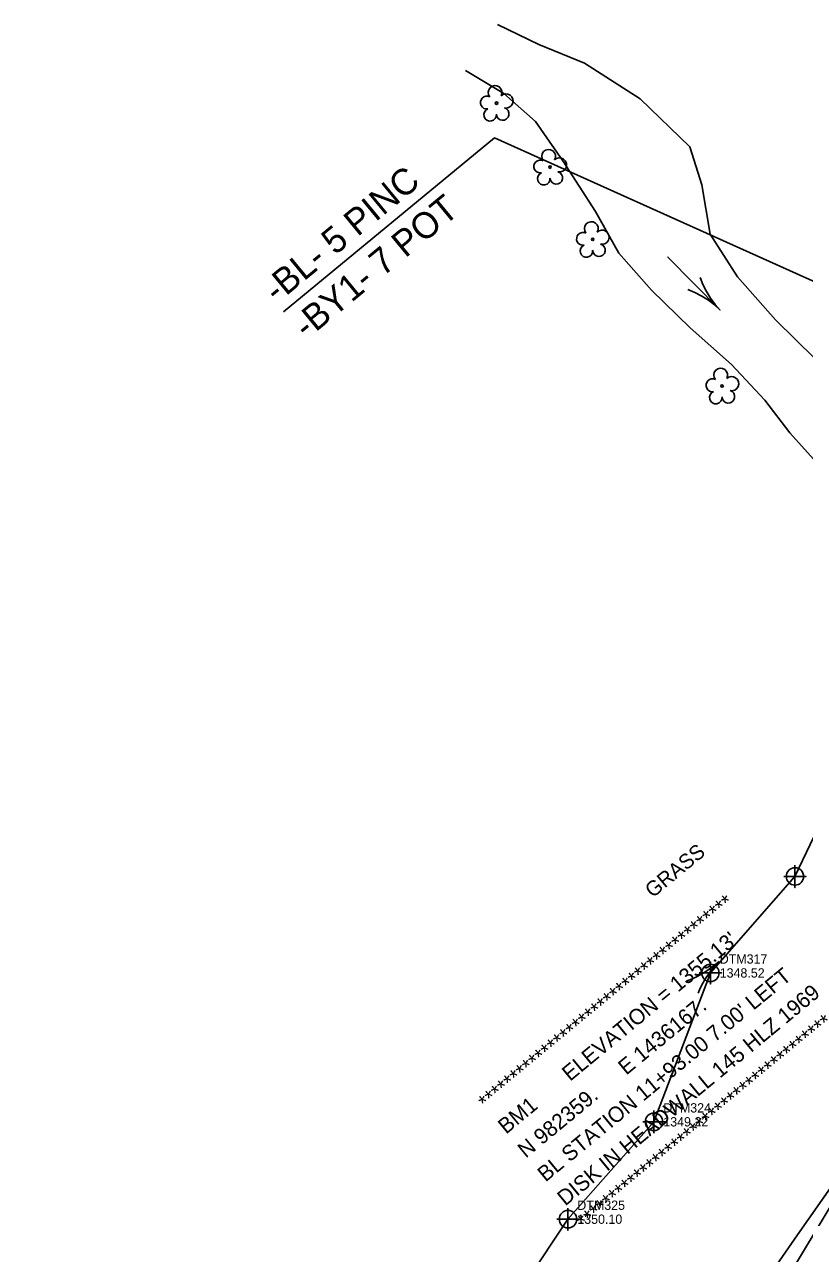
# Model space of a CAD drawing. Extents: x 1435573 to 1437263, y 981340 to 982884.
# Drawn here: x 1435866.4 to 1436076, y 982245.5 to 982575.5 of the extents above; entities that cross this region are included whole.
import ezdxf

# ---------------------------------------------------------------- set-up
doc = ezdxf.new("R2010")
doc.units = 0
for name, color, linetype in [('CTL Sheet Text', 7, 'Continuous'), ('Exist Horizontal Baseline Alignment Station Label', 7, 'Continuous'), ('Exist Hydro Jurisdictional Stream or Body of Water', 7, 'Continuous'), ('Exist Hydro River Flow Arrow CELL', 7, 'Continuous'), ('Exist Hydro Stream Flow Arrow CELL', 7, 'Continuous'), ('Exist Hydro Stream or Body of Water Cogo Elevation', 7, 'Continuous'), ('Exist Hydro Stream or Body of Water Cogo Number', 7, 'Continuous'), ('Exist Hydro Stream or Body of Water Cogo Point CELL', 7, 'Continuous'), ('Exist Other Culture Fence Line', 7, 'Continuous'), ('Exist Roads EOP', 7, 'Continuous'), ('Exist Vegetation Shrub Text', 7, 'Continuous'), ('Exist Vegetation Tree CELL', 7, 'Continuous'), ('Exist Vegetation Woods Line', 7, 'Continuous')]:
    doc.layers.add(name, color=color, linetype=linetype)

msp = doc.modelspace()

# ---------------------------------------------------------------- linework, layer by layer
at = {"layer": 'Exist Horizontal Baseline Alignment Station Label'}
for p in [(1435936.03, 982498.36), (1436220.79, 982442.59)]:
    msp.add_line(p, (1435992.65, 982545.09), dxfattribs=at)
at = {"layer": 'Exist Hydro Jurisdictional Stream or Body of Water'}
for points in [[(1435993.51, 982575.54), (1436004.62, 982570.21), (1436016.87, 982565.15), (1436031.87, 982555.63), (1436045.15, 982542.72), (1436048.39, 982532.48), (1436050.69, 982519.28), (1436057.99, 982507.82), (1436068.19, 982496.23), (1436078.82, 982485.77), (1436087.08, 982476.93)], [(1435984.89, 982563.21), (1435995.23, 982557), (1436003.7, 982549.49), (1436011.02, 982538.95), (1436019.83, 982525.32), (1436026.07, 982514.13), (1436034.87, 982504.24), (1436045.28, 982494.14), (1436056.39, 982484.25), (1436065.35, 982474.68), (1436072.03, 982465.87)], [(1436091.98, 982443.75), (1436072.03, 982465.87)], [(1435868.19, 982015.59), (1435900.37, 982051.1), (1435890.46, 982068.11), (1435899.75, 982073.74), (1435922.56, 982111.64), (1435976.46, 982187.79), (1435990.17, 982221.39), (1436012.44, 982254.73), (1436035.55, 982280.88), (1436050.71, 982320.86), (1436073.43, 982346.77), (1436085.85, 982372.72), (1436095.83, 982388.72), (1436115.7, 982405.3)]]:
    msp.add_lwpolyline(points, dxfattribs=at)
at = {"layer": 'Exist Hydro River Flow Arrow CELL'}
msp.add_line((1436046.31, 982506), (1436046.31, 982506), dxfattribs=at)
msp.add_lwpolyline([(1436047.93, 982507.61), (1436048.7, 982505.71), (1436049.63, 982503.86), (1436050.73, 982502.08), (1436051.95, 982500.4), (1436053.33, 982498.89), (1436039.28, 982513.12), (1436053.33, 982498.89), (1436051.84, 982500.29), (1436050.18, 982501.53), (1436048.41, 982502.65), (1436046.57, 982503.6), (1436044.68, 982504.39)], dxfattribs=at)
at = {"layer": 'Exist Hydro Stream Flow Arrow CELL'}
msp.add_line((1436049.43, 982320.5), (1436049.43, 982320.5), dxfattribs=at)
for points in [[(1436044.23, 982318.69), (1436045.61, 982319.18), (1436046.96, 982319.84), (1436048.28, 982320.5), (1436049.52, 982321.25), (1436050.74, 982322.1), (1436051.92, 982323.01), (1436053.03, 982323.97)], [(1436047.4, 982315.39), (1436047.95, 982316.75), (1436048.66, 982318.07), (1436049.38, 982319.36), (1436050.18, 982320.57), (1436051.07, 982321.75), (1436052.03, 982322.9), (1436053.03, 982323.97)]]:
    msp.add_lwpolyline(points, dxfattribs=at)
at = {"layer": 'Exist Hydro Stream or Body of Water Cogo Point CELL'}
for points in [[(1436070.43, 982346.77), (1436076.43, 982346.77), (1436073.43, 982346.77), (1436073.43, 982343.77), (1436073.43, 982349.77)], [(1436047.71, 982320.86), (1436053.71, 982320.86), (1436050.71, 982320.86), (1436050.71, 982317.86), (1436050.71, 982323.86)], [(1436032.55, 982280.88), (1436038.55, 982280.88), (1436035.55, 982280.88), (1436035.55, 982277.88), (1436035.55, 982283.88)], [(1436009.44, 982254.73), (1436015.44, 982254.73), (1436012.44, 982254.73), (1436012.44, 982251.73), (1436012.44, 982257.73)]]:
    msp.add_lwpolyline(points, dxfattribs=at)
for centre in [(1436073.43, 982346.77), (1436050.71, 982320.86), (1436035.55, 982280.88), (1436012.44, 982254.73)]:
    msp.add_circle(centre, 2.34, dxfattribs=at)
at = {"layer": 'Exist Other Culture Fence Line'}
msp.add_lwpolyline([(1435979.98, 982088.94), (1436003.47, 982127.28), (1436023.88, 982160.05), (1436102.97, 982291.31), (1436135.2, 982345.79), (1436142.87, 982358.83), (1436158.39, 982359.45)], dxfattribs=at)
at = {"layer": 'Exist Roads EOP'}
for points in [[(1436168.25, 982354.25), (1436159.59, 982341.51), (1436138.87, 982307.92), (1436116.45, 982270.71), (1436094.59, 982234.3), (1436072.39, 982197.46), (1436049.68, 982158.52), (1436026.6, 982119.74), (1436003.23, 982078.86), (1435983.99, 982044.69), (1435963.78, 982007.01), (1435943.65, 981966.84), (1435922.15, 981922.09), (1435903.52, 981881.23), (1435884.45, 981840.59), (1435866.4, 981798.52)], [(1436177.12, 982349.86), (1436168.84, 982336.18), (1436150.23, 982301.68), (1436128.75, 982263.64), (1436107.21, 982226.88), (1436085.56, 982190.23), (1436062.44, 982151.3), (1436039.53, 982112.34), (1436015.81, 982071.47), (1435996.75, 982037.94), (1435976.48, 982000.31), (1435956.5, 981960.4), (1435935.19, 981915.99), (1435916.41, 981875.42), (1435898.23, 981835.84), (1435879.29, 981793.08)]]:
    msp.add_spline(points, degree=3, dxfattribs=at)
at = {"layer": 'Exist Vegetation Tree CELL'}
for p, q in [((1435993.24, 982554.43), (1435993.24, 982554.43)), ((1436007.62, 982537.26), (1436007.62, 982537.26)), ((1436019.08, 982517.86), (1436019.08, 982517.86)), ((1436053.86, 982478.51), (1436053.86, 982478.51))]:
    msp.add_line(p, q, dxfattribs=at)
for centre in [(1435993.24, 982554.43), (1436007.62, 982537.26), (1436019.08, 982517.86), (1436053.86, 982478.51)]:
    msp.add_circle(centre, 0.326, dxfattribs=at)
for centre, radius, start, end in [((1435992.86, 982557.31), 1.86, 330.1651, 219.7134), ((1435990.64, 982554.59), 1.73, 62.6636, 279.3457), ((1435995.79, 982555.02), 1.9, 257.1011, 134.1999), ((1435991.54, 982551.31), 1.69, 111.5671, 6.231), ((1435994.91, 982551.53), 1.7, 181.2822, 74.56), ((1436005.01, 982537.42), 1.73, 62.6636, 279.3457), ((1436007.23, 982540.14), 1.86, 330.1651, 219.7134), ((1436010.17, 982537.85), 1.9, 257.1011, 134.1999), ((1436005.92, 982534.14), 1.69, 111.5671, 6.231), ((1436009.29, 982534.37), 1.7, 181.2822, 74.56), ((1436018.7, 982520.74), 1.86, 330.1651, 219.7134), ((1436016.48, 982518.02), 1.73, 62.6636, 279.3457), ((1436021.63, 982518.45), 1.9, 257.1011, 134.1999), ((1436017.38, 982514.74), 1.69, 111.5671, 6.231), ((1436020.76, 982514.96), 1.7, 181.2822, 74.56), ((1436053.47, 982481.38), 1.86, 330.1651, 219.7134), ((1436051.25, 982478.66), 1.73, 62.6636, 279.3457), ((1436056.41, 982479.1), 1.9, 257.1011, 134.1999), ((1436052.15, 982475.39), 1.69, 111.5671, 6.231), ((1436055.53, 982475.61), 1.7, 181.2822, 74.56)]:
    msp.add_arc(centre, radius, start, end, dxfattribs=at)
at = {"layer": 'Exist Vegetation Woods Line'}
msp.add_lwpolyline([(1436022.3, 982179.95), (1436034.94, 982194.02), (1436044.86, 982209.69), (1436061.4, 982232.18), (1436074.09, 982250.54), (1436083.63, 982264.01), (1436092.08, 982271.21), (1436099.98, 982265.71), (1436088.34, 982245.67), (1436068.18, 982213.85), (1436049.75, 982183.61), (1436035.71, 982164.59), (1436028.24, 982156.34), (1436019.56, 982156.9), (1436018.12, 982165.84), (1436022.3, 982179.95)], dxfattribs=at)

# ---------------------------------------------------------------- texts
at = {"layer": 'CTL Sheet Text'}
for s, p in [('****************************************', (1435990.49, 982283.84)), ("BM1       ELEVATION = 1355.13'", (1435995.8, 982277.41)), ("BL STATION 11+93.00 7.00' LEFT", (1436006.41, 982264.56)), ('DISK IN HEADWALL 145 HLZ 1969', (1436011.71, 982258.13)), ('N 982359.      E 1436167.', (1436001.1, 982270.98)), ('****************************************', (1436017.02, 982251.7))]:
    msp.add_text(s, height=4.1667, rotation=39.5399, dxfattribs=at).set_placement(p)
at = {"layer": 'Exist Horizontal Baseline Alignment Station Label'}
for s, p in [('-BL- 5 PINC   ', (1435934.23, 982500.54)), ('-BY1- 7 POT   ', (1435942.23, 982490.85))]:
    msp.add_text(s, height=7, rotation=39.5399, dxfattribs=at).set_placement(p)
at = {"layer": 'Exist Hydro Stream or Body of Water Cogo Elevation'}
for s, p in [('1348.52', (1436053.21, 982319.61)), ('1349.22', (1436038.05, 982279.63)), ('1350.10', (1436014.94, 982253.48))]:
    msp.add_text(s, height=2.5, dxfattribs=at).set_placement(p)
at = {"layer": 'Exist Hydro Stream or Body of Water Cogo Number'}
for s, p in [('DTM317', (1436053.21, 982323.36)), ('DTM324', (1436038.05, 982283.38)), ('DTM325', (1436014.94, 982257.23))]:
    msp.add_text(s, height=2.5, dxfattribs=at).set_placement(p)
at = {"layer": 'Exist Vegetation Shrub Text'}
msp.add_text('GRASS', height=4, rotation=39.5399, dxfattribs=at).set_placement((1436035.22, 982340.85))

doc.saveas('drawing.dxf')
